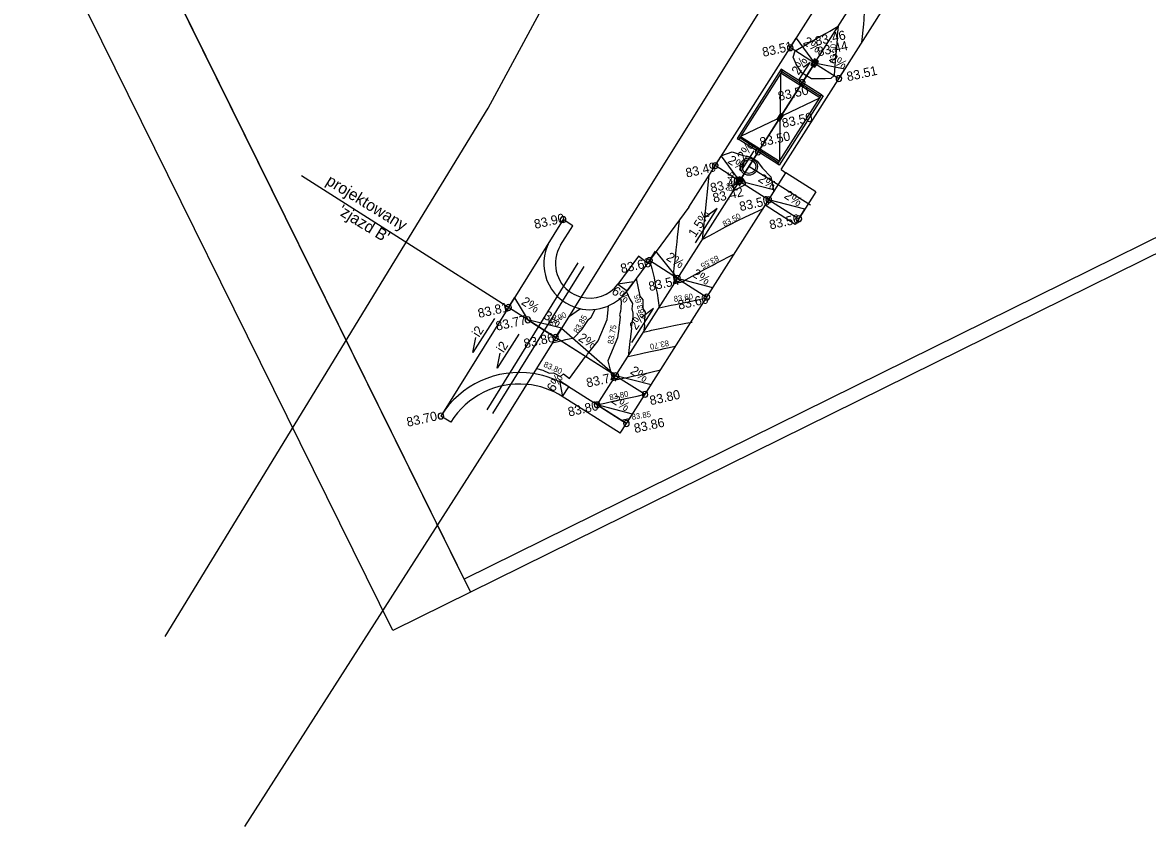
# Model space of a CAD drawing. Extents: x 6441746 to 6441901, y 5798263 to 5798406.
# Drawn here: x 6441745.6 to 6441843.1, y 5798263.3 to 5798333 of the extents above; entities that cross this region are included whole.
import ezdxf

# ---------------------------------------------------------------- set-up
doc = ezdxf.new("R2010")
doc.units = 0
for name, color, linetype in [('GEPINN', 7, 'Continuous'), ('GEPPGD', 7, 'Continuous'), ('GESBWT', 7, 'Continuous'), ('GESDZI', 7, 'Continuous'), ('GESDZI_O', 7, 'Continuous'), ('GSLBRA', 7, 'Continuous'), ('GSLKOC', 7, 'Continuous'), ('GSLKOU', 7, 'Continuous'), ('GSLOGS', 7, 'Continuous'), ('GSLPRZ', 7, 'Continuous'), ('GSLSKN', 7, 'Continuous'), ('GSLWSD', 7, 'Continuous'), ('GSPDIP', 7, 'Continuous'), ('GSPDLP', 7, 'Continuous'), ('GSPINN', 7, 'Continuous'), ('GSPPIK', 7, 'Continuous')]:
    doc.layers.add(name, color=color, linetype=linetype)

# ---------------------------------------------------------------- blocks, each defined once
blk = doc.blocks.new('A$C720754CC')
at = {"layer": 'GSPDIP'}
blk.add_lwpolyline([(-0.092, -0.352), (0.354, 0.05), (0.086, 0.347), (-0.359, -0.055)], close=True, dxfattribs=at)
blk.add_lwpolyline([(0.005, -0.265), (-0.263, 0.032), (-0.134, 0.149), (0.134, -0.149), (0.246, -0.048), (-0.022, 0.249)], dxfattribs=at)
blk = doc.blocks.new('_DotSmall')
for start, end in [(0, 180), (180, 0)]:
    blk.add_arc((0, 0), 0.0625, start, end)

msp = doc.modelspace()

# ---------------------------------------------------------------- linework, layer by layer
at = {"layer": 'GEPINN'}
for p, q in [((6441792.462, 5798315.889), (6441781.877, 5798298.871)), ((6441792.255, 5798313.662), (6441793.311, 5798315.361)), ((6441793.311, 5798315.361), (6441792.462, 5798315.889)), ((6441793.751, 5798312.154), (6441785.845, 5798299.406)), ((6441794.261, 5798311.837), (6441786.355, 5798299.09)), ((6441782.726, 5798298.343), (6441781.877, 5798298.871))]:
    msp.add_line(p, q, dxfattribs=at)
for centre, radius, start, end in [((6441794.795, 5798312.083), 4, 151.95069, 250.77007), ((6441794.802, 5798312.078), 3, 148.11784, 237.53667), ((6441794.795, 5798312.083), 3, 237.53667, 255.12454), ((6441788.67, 5798294.646), 8, 81.23945, 148.11784), ((6441788.67, 5798294.646), 7, 84.79628, 148.11784)]:
    msp.add_arc(centre, radius, start, end, dxfattribs=at)
at = {"layer": 'GESBWT'}
for p, q in [((6441814.38, 5798318.298), (6441811.78, 5798319.952)), ((6441814.38, 5798318.298), (6441812.588, 5798315.478)), ((6441812.588, 5798315.478), (6441809.986, 5798317.133)), ((6441798.989, 5798312.718), (6441797.21, 5798310.303)), ((6441799.794, 5798312.125), (6441798.989, 5798312.718)), ((6441797.418, 5798297.377), (6441792.31, 5798300.626)), ((6441797.418, 5798297.377), (6441797.955, 5798298.22))]:
    msp.add_line(p, q, dxfattribs=at)
for centre, radius, start, end in [((6441794.795, 5798312.083), 3, 255.12454, 323.61445), ((6441788.67, 5798294.646), 7, 57.53667, 84.79628)]:
    msp.add_arc(centre, radius, start, end, dxfattribs=at)
at = {"layer": 'GESDZI'}
for p, q in [((6441811.358, 5798320.221), (6441833.228, 5798354.598)), ((6441803.361, 5798316.966), (6441825.245, 5798351.365)), ((6441797.955, 5798298.22), (6441811.78, 5798319.952)), ((6441803.361, 5798316.966), (6441798.015, 5798309.71)), ((6441797.955, 5798298.22), (6441792.846, 5798301.47))]:
    msp.add_line(p, q, dxfattribs=at)
for centre, radius, start, end in [((6441794.795, 5798312.083), 4, 250.77007, 323.61445), ((6441788.67, 5798294.646), 8, 57.53667, 81.23945)]:
    msp.add_arc(centre, radius, start, end, dxfattribs=at)
at = {"layer": 'GSLBRA'}
for points in [[(6441745.614, 5798345.296), (6441868.651, 5798406.04), (6441900.746, 5798341.031), (6441777.709, 5798280.287)], [(6441752.892, 5798347.495), (6441868.083, 5798404.366), (6441899.072, 5798341.599), (6441783.881, 5798284.728)]]:
    msp.add_lwpolyline(points, close=True, dxfattribs=at)
at = {"layer": 'GSLKOC'}
for points in [[(6441757.985, 5798279.781), (6441785.979, 5798325.557), (6441801.634, 5798354.549), (6441815.402, 5798382.645), (6441824.514, 5798403.306)], [(6441841.564, 5798403.306), (6441827.893, 5798374.814), (6441812.231, 5798338.37), (6441797.846, 5798315.309), (6441786.869, 5798297.713), (6441764.868, 5798263.306)]]:
    msp.add_lwpolyline(points, dxfattribs=at)
at = {"layer": 'GSLKOU'}
msp.add_lwpolyline([(6441745.614, 5798345.296), (6441752.339, 5798348.616), (6441784.434, 5798283.607), (6441777.709, 5798280.287)], close=True, dxfattribs=at)
at = {"layer": 'GSLPRZ'}
for points in [[(6441818.363, 5798331.232), (6441818.528, 5798332.835), (6441818.553, 5798333.234), (6441818.596, 5798333.927), (6441818.664, 5798334.589), (6441818.707, 5798334.996), (6441818.766, 5798335.955), (6441818.775, 5798336.088), (6441818.829, 5798336.622), (6441818.369, 5798336.346), (6441818.252, 5798336.282), (6441817.409, 5798335.822), (6441817.058, 5798335.611), (6441816.487, 5798335.268), (6441815.879, 5798334.937), (6441815.527, 5798334.745), (6441814.143, 5798333.914)], [(6441807.223, 5798318.38), (6441807.339, 5798319.492), (6441807.396, 5798319.506), (6441807.401, 5798319.514), (6441807.549, 5798319.601), (6441807.967, 5798319.549), (6441808.23, 5798319.156), (6441808.248, 5798318.964), (6441808.267, 5798318.902), (6441808.246, 5798318.89), (6441807.223, 5798318.38)], [(6441802.519, 5798315.822), (6441802.363, 5798314.366), (6441802.317, 5798313.966), (6441802.241, 5798313.258), (6441802.166, 5798312.613), (6441802.116, 5798312.151), (6441802.059, 5798311.7), (6441802.04, 5798311.379), (6441801.997, 5798311.039), (6441801.997, 5798311.039), (6441802.125, 5798310.364), (6441802.805, 5798310.503), (6441802.805, 5798310.503), (6441803.122, 5798310.69), (6441804.185, 5798311.273), (6441804.747, 5798311.594), (6441805.389, 5798311.927), (6441805.74, 5798312.124), (6441807.307, 5798312.921)], [(6441798.811, 5798310.791), (6441799.122, 5798309.261), (6441799.369, 5798308.94), (6441799.387, 5798308.242), (6441799.499, 5798308.005), (6441799.582, 5798307.865), (6441799.497, 5798306.833), (6441799.509, 5798306.768), (6441799.507, 5798306.718), (6441799.441, 5798306.146), (6441799.963, 5798306.259), (6441800.14, 5798306.297), (6441801.007, 5798306.485), (6441801.537, 5798306.599), (6441802.05, 5798306.709), (6441802.971, 5798306.877), (6441803.116, 5798306.907), (6441803.651, 5798307.018)], [(6441797.451, 5798309.092), (6441797.509, 5798308.772), (6441797.484, 5798308.218), (6441797.451, 5798307.932), (6441797.367, 5798307.643), (6441797.409, 5798307.465), (6441797.348, 5798306.952), (6441797.319, 5798306.74), (6441797.307, 5798306.572), (6441797.285, 5798306.428), (6441797.192, 5798305.638), (6441796.357, 5798303.656), (6441796.481, 5798303.073), (6441796.507, 5798302.967), (6441796.589, 5798302.645), (6441796.761, 5798301.942), (6441797.455, 5798302.093), (6441797.799, 5798302.167), (6441797.914, 5798302.194), (6441798.488, 5798302.32), (6441799.351, 5798302.512), (6441800.907, 5798302.861)], [(6441791.558, 5798305.224), (6441792.268, 5798305.394), (6441792.696, 5798305.509), (6441792.842, 5798305.535), (6441793.384, 5798305.647), (6441794.08, 5798306.36), (6441794.315, 5798306.709), (6441794.666, 5798307.236), (6441794.903, 5798307.424), (6441795.235, 5798308.107)], [(6441798.225, 5798298.641), (6441798.198, 5798298.628), (6441797.532, 5798298.49)]]:
    msp.add_lwpolyline(points, dxfattribs=at)
at = {"layer": 'GSLWSD'}
for p, q in [((6441795.423, 5798299.831), (6441836.479, 5798364.366)), ((6441797.034, 5798302.362), (6441769.801, 5798319.687))]:
    msp.add_line(p, q, dxfattribs=at)
at = {"layer": 'GSPDLP'}
for points in [[(6441813.689, 5798331.138), (6441814.193, 5798331.44), (6441814.609, 5798331.69), (6441815.382, 5798332.112), (6441815.57, 5798332.214), (6441816.307, 5798332.657), (6441816.219, 5798331.802), (6441816.205, 5798331.589), (6441816.151, 5798330.71), (6441816.1, 5798330.226), (6441816.04, 5798329.641), (6441815.983, 5798328.788), (6441815.965, 5798328.477), (6441815.952, 5798328.374), (6441815.662, 5798328.103), (6441815.18, 5798328.09), (6441813.99, 5798328.083), (6441813.708, 5798328.262), (6441813.568, 5798328.351), (6441813.427, 5798328.44), (6441813.145, 5798328.619), (6441812.683, 5798329.29), (6441812.394, 5798329.966), (6441812.58, 5798330.524), (6441813.135, 5798330.834), (6441813.689, 5798331.138)], [(6441806.214, 5798321.449), (6441807.126, 5798321.774), (6441808.071, 5798321.457), (6441808.694, 5798321.335), (6441808.889, 5798321.212), (6441808.986, 5798321.15), (6441809.084, 5798321.088), (6441809.279, 5798320.964), (6441809.749, 5798320.354), (6441810.474, 5798319.597), (6441810.73, 5798318.302)], [(6441809.795, 5798316.832), (6441808.554, 5798316.253), (6441808.25, 5798316.095), (6441807.525, 5798315.748), (6441806.982, 5798315.459), (6441806.513, 5798315.23), (6441805.746, 5798314.814), (6441805.519, 5798314.701), (6441804.54, 5798314.162), (6441804.664, 5798315.269), (6441804.69, 5798315.521), (6441804.784, 5798316.378), (6441804.837, 5798316.895), (6441804.901, 5798317.489), (6441804.981, 5798318.284), (6441805.015, 5798318.602), (6441805.127, 5798319.741)], [(6441799.952, 5798312.339), (6441800.161, 5798311.661), (6441800.361, 5798310.843), (6441800.484, 5798310.088), (6441800.618, 5798309.523), (6441800.783, 5798308.255), (6441801.834, 5798308.473), (6441802.196, 5798308.548), (6441803.978, 5798308.911), (6441804.228, 5798308.964), (6441804.868, 5798309.087)], [(6441797.954, 5798309.627), (6441798.254, 5798308.993), (6441798.475, 5798308.619), (6441798.437, 5798308.161), (6441798.509, 5798307.77), (6441798.496, 5798307.468), (6441798.408, 5798306.706), (6441798.371, 5798306.577), (6441798.389, 5798306.498), (6441798.268, 5798305.473), (6441798.26, 5798305.412), (6441798.257, 5798305.364), (6441798.25, 5798305.323), (6441798.099, 5798304.038), (6441799.137, 5798304.27), (6441799.497, 5798304.339), (6441800.187, 5798304.488), (6441800.894, 5798304.641), (6441801.23, 5798304.713), (6441802.222, 5798304.928)], [(6441790.163, 5798302.992), (6441790.704, 5798302.851), (6441791.263, 5798302.598), (6441791.642, 5798302.618), (6441792.227, 5798302.305), (6441792.513, 5798302.523), (6441793.02, 5798302.127), (6441794.418, 5798304.026), (6441794.518, 5798304.105), (6441794.531, 5798304.131), (6441794.549, 5798304.171), (6441794.58, 5798304.236), (6441795.508, 5798305.396), (6441796.284, 5798307.237), (6441796.319, 5798307.534), (6441796.357, 5798307.78), (6441796.405, 5798308.421)], [(6441793.963, 5798308.17), (6441792.936, 5798307.432)], [(6441795.401, 5798299.846), (6441796.095, 5798299.997), (6441796.326, 5798300.047), (6441796.788, 5798300.147), (6441797.482, 5798300.298), (6441798.176, 5798300.45), (6441798.874, 5798300.598), (6441799.564, 5798300.752)], [(6441795.4, 5798299.845), (6441795.376, 5798299.86), (6441795.401, 5798299.846), (6441795.4, 5798299.845)]]:
    msp.add_lwpolyline(points, dxfattribs=at)
at = {"layer": 'GSPINN'}
for p, q in [((6441811.369, 5798328.912), (6441807.564, 5798322.917)), ((6441814.254, 5798329.431), (6441807.761, 5798319.224)), ((6441811.495, 5798328.832), (6441811.369, 5798328.912)), ((6441811.334, 5798328.578), (6441807.851, 5798323.09)), ((6441811.316, 5798325.096), (6441811.334, 5798328.578)), ((6441811.334, 5798328.578), (6441811.495, 5798328.832)), ((6441814.712, 5798326.435), (6441811.334, 5798328.578)), ((6441814.792, 5798326.562), (6441811.415, 5798328.705)), ((6441814.872, 5798326.688), (6441811.495, 5798328.832)), ((6441814.999, 5798326.608), (6441811.194, 5798320.613)), ((6441811.229, 5798320.947), (6441814.712, 5798326.435)), ((6441811.569, 5798324.935), (6441814.712, 5798326.435)), ((6441814.712, 5798326.435), (6441814.872, 5798326.688)), ((6441814.872, 5798326.688), (6441814.999, 5798326.608)), ((6441811.316, 5798325.096), (6441810.994, 5798324.59)), ((6441811.515, 5798324.851), (6441811.262, 5798325.012)), ((6441811.569, 5798324.935), (6441811.316, 5798325.096)), ((6441810.994, 5798324.59), (6441807.851, 5798323.09)), ((6441810.994, 5798324.59), (6441811.247, 5798324.429)), ((6441811.301, 5798324.513), (6441811.048, 5798324.674)), ((6441811.355, 5798324.598), (6441811.101, 5798324.759)), ((6441811.408, 5798324.682), (6441811.155, 5798324.843)), ((6441811.462, 5798324.767), (6441811.208, 5798324.927)), ((6441811.247, 5798324.429), (6441811.229, 5798320.947)), ((6441811.247, 5798324.429), (6441811.569, 5798324.935)), ((6441807.691, 5798322.837), (6441807.851, 5798323.09)), ((6441807.851, 5798323.09), (6441811.229, 5798320.947)), ((6441807.564, 5798322.917), (6441807.691, 5798322.837)), ((6441811.068, 5798320.694), (6441807.691, 5798322.837)), ((6441811.148, 5798320.82), (6441807.771, 5798322.964)), ((6441813.902, 5798317.149), (6441808.563, 5798320.485)), ((6441811.068, 5798320.694), (6441811.229, 5798320.947)), ((6441811.194, 5798320.613), (6441811.068, 5798320.694)), ((6441811.358, 5798320.221), (6441811.78, 5798319.952))]:
    msp.add_line(p, q, dxfattribs=at)
for radius in [0.75, 0.6]:
    msp.add_circle((6441808.563, 5798320.485), radius, dxfattribs=at)
at = {"layer": 'GSPPIK'}
for points in [[(6441814.267, 5798329.451), (6441812.159, 5798330.793), (6441812.679, 5798331.611)], [(6441814.267, 5798329.451), (6441816.376, 5798328.11), (6441816.897, 5798328.928)], [(6441807.761, 5798319.224), (6441805.652, 5798320.565), (6441806.173, 5798321.383)], [(6441807.761, 5798319.224), (6441810.292, 5798317.613), (6441810.813, 5798318.432)], [(6441810.292, 5798317.613), (6441812.9, 5798315.969), (6441813.421, 5798316.787)], [(6441802.393, 5798310.786), (6441799.952, 5798312.339), (6441800.473, 5798313.157)], [(6441797.21, 5798310.303), (6441798.015, 5798309.71), (6441798.59, 5798310.491)], [(6441802.393, 5798310.786), (6441804.933, 5798309.17), (6441805.454, 5798309.988)], [(6441789.417, 5798307.207), (6441787.73, 5798308.281), (6441788.25, 5798309.099)], [(6441789.417, 5798307.207), (6441791.822, 5798305.678), (6441792.342, 5798306.496)], [(6441797.034, 5798302.362), (6441791.822, 5798305.678), (6441792.342, 5798306.496)], [(6441792.427, 5798300.552), (6441792.963, 5798301.395), (6441792.145, 5798301.915)], [(6441797.034, 5798302.362), (6441799.565, 5798300.752), (6441800.085, 5798301.57)], [(6441795.426, 5798299.829), (6441797.957, 5798298.219), (6441798.478, 5798299.037)]]:
    msp.add_lwpolyline(points, close=True, dxfattribs=at)
for points in [[(6441812.927, 5798328.027), (6441813.867, 5798329.503), (6441813.327, 5798329.106)], [(6441808.992, 5798321.84), (6441808.053, 5798320.364), (6441808.184, 5798321.021)], [(6441803.934, 5798313.889), (6441805.812, 5798316.841), (6441804.732, 5798316.047)], [(6441798.427, 5798305.234), (6441800.306, 5798308.186), (6441799.226, 5798307.392)], [(6441786.515, 5798307.315), (6441784.637, 5798304.362), (6441784.898, 5798305.677)], [(6441788.629, 5798305.969), (6441786.751, 5798303.017), (6441787.013, 5798304.332)]]:
    msp.add_lwpolyline(points, dxfattribs=at)

# ---------------------------------------------------------------- block references
at = {"layer": 'GSLSKN', "xscale": 4, "yscale": 4}
for p in [(6441812.155, 5798330.788), (6441814.264, 5798329.446), (6441813.191, 5798327.759), (6441816.374, 5798328.104), (6441809.378, 5798321.766), (6441805.651, 5798320.565), (6441807.761, 5798319.224), (6441810.292, 5798317.613), (6441812.9, 5798315.969), (6441792.462, 5798315.889), (6441799.952, 5798312.339), (6441802.393, 5798310.786), (6441804.926, 5798309.179), (6441787.73, 5798308.281), (6441789.417, 5798307.207), (6441791.822, 5798305.678), (6441797.034, 5798302.362), (6441799.565, 5798300.751), (6441795.423, 5798299.831), (6441781.877, 5798298.871), (6441797.955, 5798298.22)]:
    msp.add_blockref('_DotSmall', p, dxfattribs=at)
at = {"layer": 'GSPINN', "rotation": -164.4116379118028}
for p in [(6441814.264, 5798329.446), (6441807.761, 5798319.224)]:
    msp.add_blockref('A$C720754CC', p, dxfattribs=at)

# ---------------------------------------------------------------- texts
at = {"layer": 'GEPPGD'}
for s, rotation, p in [('83.45', 84.09405, (6441807.092, 5798318.326)), ('83.55', 207.78319, (6441805.805, 5798312.819)), ('83.65', 104.07148, (6441799.494, 5798307.833)), ('83.85', 60.7762, (6441793.761, 5798305.992)), ('83.75', 79.28897, (6441796.796, 5798305.072)), ('83.85', 8.88465, (6441798.452, 5798298.545))]:
    msp.add_text(s, height=0.5, rotation=rotation, dxfattribs=at).set_placement(p)
at = {"layer": 'GESDZI_O'}
for s, p in [('projektowany ', (6441771.836, 5798319)), ("'zjazd B'", (6441772.875, 5798316.408))]:
    msp.add_text(s, height=1, rotation=328.48721, dxfattribs=at).set_placement(p)
at = {"layer": 'GSLOGS'}
for s, rotation, p in [('83.50', 88.12267, (6441816.09, 5798329.426)), ('83.50', 28.11341, (6441806.448, 5798315.249)), ('83.60', 8.7486, (6441802.097, 5798308.757)), ('83.90', 28.65512, (6441791.353, 5798306.678)), ('83.70', 192.18527, (6441801.582, 5798305.448)), ('83.80', 335.90328, (6441790.724, 5798303.165)), ('83.80', 11.97773, (6441796.526, 5798300.231))]:
    msp.add_text(s, height=0.5, rotation=rotation, dxfattribs=at).set_placement(p)
at = {"layer": 'GSLSKN'}
for s, p in [('83.46', (6441814.401, 5798330.947)), ('83.51', (6441809.819, 5798329.988)), ('83.44', (6441814.588, 5798330.029)), ('83.51', (6441817.138, 5798327.87)), ('83.50', (6441811.182, 5798326.172)), ('83.50', (6441809.602, 5798322.19)), ('83.49', (6441803.177, 5798319.526)), ('83.44', (6441805.315, 5798318.229)), ('83.50', (6441807.838, 5798316.617)), ('83.90', (6441790.048, 5798315.086)), ('83.56', (6441810.432, 5798315.029)), ('83.60', (6441797.538, 5798311.242)), ('83.54', (6441799.972, 5798309.688)), ('83.60', (6441802.512, 5798308.081)), ('83.81', (6441785.174, 5798307.364)), ('83.77', (6441786.729, 5798306.26)), ('83.86', (6441789.151, 5798304.735)), ('83.74', (6441794.568, 5798301.336)), ('83.80', (6441800.06, 5798299.805)), ('83.80', (6441792.977, 5798298.822)), ('83.70', (6441778.997, 5798297.933)), ('83.86', (6441798.705, 5798297.393))]:
    msp.add_text(s, height=0.8, rotation=12.53667, dxfattribs=at).set_placement(p)
at = {"layer": 'GSPINN'}
for s, p in [('83.50', (6441811.532, 5798323.832)), ('83.42', (6441805.534, 5798317.356))]:
    msp.add_text(s, height=0.8, rotation=12.53667, dxfattribs=at).set_placement(p)
at = {"layer": 'GSPPIK'}
for s, rotation, p in [('2%', 327.53667, (6441813.197, 5798331.121)), ('2%', 57.53727, (6441812.874, 5798328.359)), ('2%', 327.53667, (6441815.449, 5798329.688)), ('2%', 57.53667, (6441808.169, 5798320.963)), ('2%', 327.53667, (6441806.661, 5798320.846)), ('2%', 327.53667, (6441809.295, 5798319.259)), ('2%', 327.53667, (6441811.551, 5798317.816)), ('1,5%', 57.53667, (6441803.925, 5798314.292)), ('2%', 327.53667, (6441801.331, 5798312.45)), ('2%', 327.53667, (6441803.584, 5798311.017)), ('6%', 323.63626, (6441796.606, 5798309.531)), ('2%', 327.53667, (6441788.776, 5798308.599)), ('3%', 327.53667, (6441790.697, 5798307.377)), ('2%', 57.53667, (6441798.815, 5798306.26)), ('i2', 57.53667, (6441785.19, 5798305.648)), ('2%', 327.53667, (6441793.717, 5798305.456)), ('i2', 57.53667, (6441787.304, 5798304.303)), ('2%', 327.53667, (6441798.215, 5798302.598)), ('6%', 57.53667, (6441791.662, 5798300.902)), ('2%', 327.53667, (6441796.608, 5798300.065))]:
    msp.add_text(s, height=0.8, rotation=rotation, dxfattribs=at).set_placement(p)

doc.saveas('drawing.dxf')
